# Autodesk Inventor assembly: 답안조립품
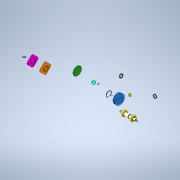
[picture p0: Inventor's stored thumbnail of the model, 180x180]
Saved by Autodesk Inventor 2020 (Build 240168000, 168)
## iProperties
Created: 2021-07
Part Number: 답안조립품
Document SubType Name: Assembly
Designer: Owner
Author: Owner
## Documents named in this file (17)
- C:\Users\Owner\Desktop\71070V1001\답안조립품.iam
- C:\Users\Owner\Desktop\71070V1001\본체.ipt
- C:\Users\Owner\Desktop\71070V1001\M16 너트.ipt
- C:\Users\Owner\Desktop\71070V1001\V-벨트풀리.ipt
- C:\Users\Owner\Desktop\71070V1001\멈춤나사 M4.ipt
- C:\Users\Owner\Desktop\71070V1001\멈춤링 62x65x2.ipt
- C:\Users\Owner\Desktop\71070V1001\베어링 6206.ipt
- C:\Users\Owner\Desktop\71070V1001\볼트 M6.ipt
- C:\Users\Owner\Desktop\71070V1001\부시.ipt
- C:\Users\Owner\Desktop\71070V1001\오일실 30x42x8.ipt
- C:\Users\Owner\Desktop\71070V1001\오일실 30x45x8.ipt
- C:\Users\Owner\Desktop\71070V1001\체인 스프로킷.ipt
- C:\Users\Owner\Desktop\71070V1001\축.ipt
- C:\Users\Owner\Desktop\71070V1001\커버A.ipt
- C:\Users\Owner\Desktop\71070V1001\커버B.ipt
- C:\Users\Owner\Desktop\71070V1001\키 6x6x18.ipt
- C:\Users\Owner\Desktop\71070V1001\키 6x6x20.ipt
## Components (2 placed, 2 different names)
1. M16 너트:1
2. V-벨트풀리:1
